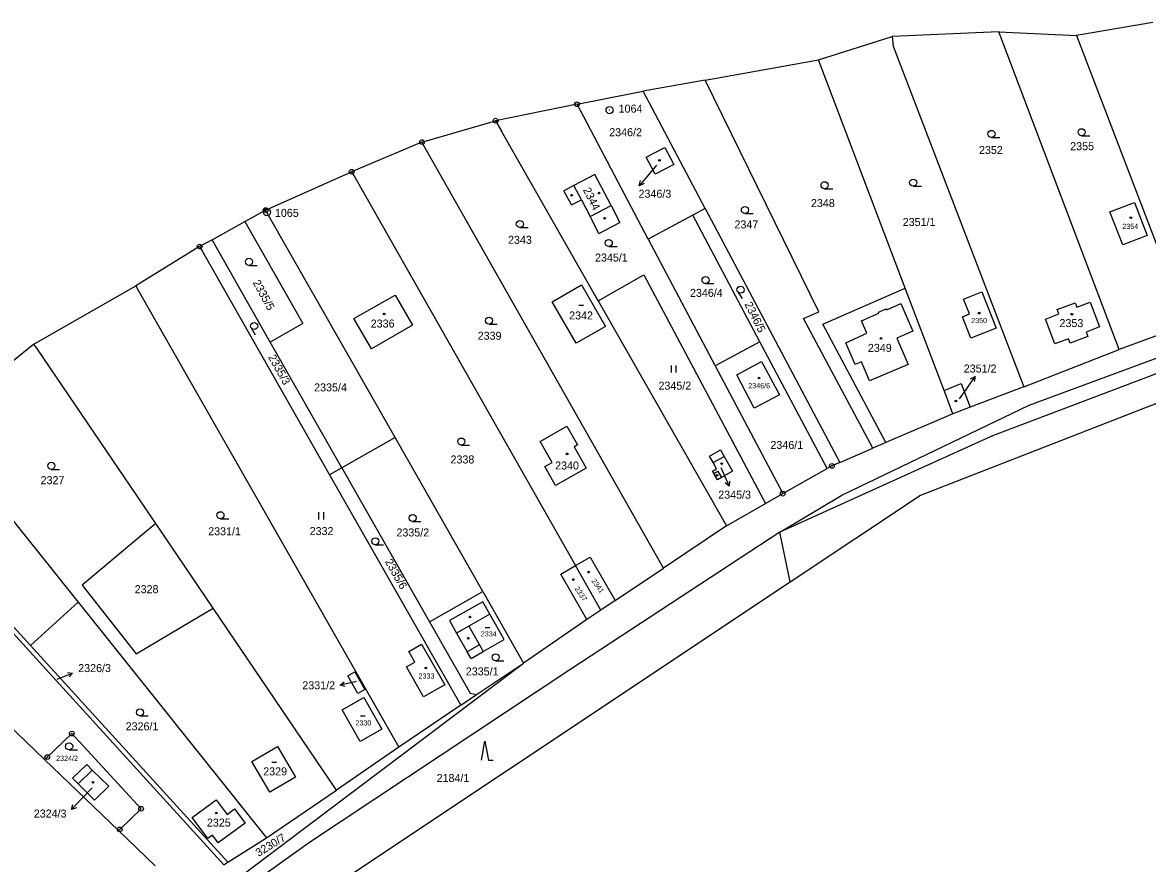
# Model space of a CAD drawing. Extents: x -736345 to -729997, y -1130177 to -1122501.
# Drawn here: x -734408.5 to -734169.6, y -1128988.6 to -1128810 of the extents above; entities that cross this region are included whole.
import ezdxf

# ---------------------------------------------------------------- set-up
doc = ezdxf.new("R2010")
doc.units = 0
for name, color, linetype in [('Vrstva 1', 7, 'Continuous'), ('Vrstva 13', 7, 'Continuous'), ('Vrstva 16', 7, 'Continuous'), ('Vrstva 17', 7, 'Continuous'), ('Vrstva 18', 7, 'Continuous'), ('Vrstva 19', 7, 'Continuous'), ('Vrstva 25', 7, 'Continuous'), ('Vrstva 4', 7, 'Continuous')]:
    doc.layers.add(name, color=color, linetype=linetype)

msp = doc.modelspace()

# ---------------------------------------------------------------- linework, layer by layer
at = {"layer": 'Vrstva 1'}
for points in [[(-734175.55, -1128879.43), (-734201.13, -1128811.92)], [(-734223.81, -1128812.9), (-734223.55, -1128814.98)], [(-734184.68, -1128812.7), (-734161.13, -1128874.06)], [(-734223.55, -1128814.98), (-734195.81, -1128887.3)], [(-734221, -1128866.4), (-734239.43, -1128817.9)], [(-734239.4, -1128871.37), (-734263.48, -1128822.21)], [(-734263.51, -1128849.46), (-734276.7, -1128824.57)], [(-734275.58, -1128855.97), (-734290.72, -1128827.32)], [(-734308.02, -1128830.81), (-734306.73, -1128833.07)], [(-734286.23, -1128869.04), (-734306.73, -1128833.07)], [(-734272.34, -1128925.84), (-734323.66, -1128835.35)], [(-734276.01, -1128838.57), (-734272.07, -1128836.49)], [(-734272.07, -1128836.49), (-734270.17, -1128840.09)], [(-734274.11, -1128842.17), (-734276.01, -1128838.57)], [(-734270.17, -1128840.09), (-734274.11, -1128842.17)], [(-734338.58, -1128841.66), (-734337.94, -1128842.77)], [(-734337.94, -1128842.77), (-734291.04, -1128925.3)], [(-734286.93, -1128842.25), (-734291.38, -1128844.58)], [(-734283.5, -1128848.82), (-734286.93, -1128842.25)], [(-734044.47, -1128842.87), (-734217.97, -1128910.48)], [(-734291.38, -1128844.58), (-734293.5, -1128845.69)], [(-734291.92, -1128848.71), (-734293.5, -1128845.69)], [(-734291.92, -1128848.71), (-734289.8, -1128847.61)], [(-734289.8, -1128847.61), (-734287.95, -1128851.15)], [(-734329.36, -1128898.07), (-734356.86, -1128849.81)], [(-734283.5, -1128848.82), (-734281.63, -1128852.4)], [(-734263.51, -1128849.46), (-734266.15, -1128850.88)], [(-734263.51, -1128849.46), (-734234.92, -1128903.41)], [(-734177.58, -1128850.2), (-734172.35, -1128848.19)], [(-734172.35, -1128848.19), (-734169.65, -1128855.2)], [(-734361.24, -1128852.22), (-734348.92, -1128873.86)], [(-734286.07, -1128854.75), (-734287.95, -1128851.15)], [(-734286.07, -1128854.75), (-734281.63, -1128852.4)], [(-734266.15, -1128850.88), (-734275.58, -1128855.97)], [(-734251.89, -1128877.76), (-734266.15, -1128850.88)], [(-734174.84, -1128857.19), (-734177.58, -1128850.2)], [(-734355.87, -1128877.81), (-734368.24, -1128856.09)], [(-734275.58, -1128855.97), (-734261.35, -1128882.89)], [(-734169.65, -1128855.2), (-734174.84, -1128857.19)], [(-734370.86, -1128857.54), (-734370.24, -1128858.62)], [(-734370.24, -1128858.62), (-734343.28, -1128906)], [(-734104.36, -1128860.59), (-734202.48, -1128897.74)], [(-734286.23, -1128869.04), (-734276.54, -1128863.52)], [(-734276.54, -1128863.52), (-734250.69, -1128912.1)], [(-734384.45, -1128865.86), (-734383.84, -1128866.92)], [(-734295.99, -1128869.25), (-734289.75, -1128865.67)], [(-734289.75, -1128865.67), (-734284.67, -1128874.53)], [(-734238.54, -1128874.04), (-734221, -1128866.4)], [(-734212.77, -1128888.09), (-734221, -1128866.4)], [(-734383.84, -1128866.92), (-734328.54, -1128963.82)], [(-734338.14, -1128872.82), (-734329.37, -1128867.85)], [(-734329.37, -1128867.85), (-734325.69, -1128874.26)], [(-734290.93, -1128878.07), (-734295.99, -1128869.25)], [(-734286.23, -1128869.04), (-734259, -1128916.82)], [(-734208.65, -1128868.68), (-734204.73, -1128867.15)], [(-734207.37, -1128871.82), (-734208.65, -1128868.68)], [(-734204.73, -1128867.15), (-734201.71, -1128874.85)], [(-734242.6, -1128872.8), (-734239.4, -1128871.37)], [(-734188.72, -1128870.92), (-734184.95, -1128869.49)], [(-734188.37, -1128871.85), (-734188.72, -1128870.92)], [(-734184.95, -1128869.49), (-734184.6, -1128870.42)], [(-734184.6, -1128870.42), (-734181.75, -1128869.34)], [(-734181.75, -1128869.34), (-734179.74, -1128874.62)], [(-734348.92, -1128873.86), (-734355.87, -1128877.81)], [(-734334.39, -1128879.25), (-734338.14, -1128872.82)], [(-734227.87, -1128900.37), (-734242.6, -1128872.8)], [(-734225.12, -1128899.18), (-734238.54, -1128874.04)], [(-734208.88, -1128872.44), (-734207.37, -1128871.82)], [(-734207.08, -1128876.98), (-734208.88, -1128872.44)], [(-734194.67, -1128891.21), (-734144.71, -1128872.72)], [(-734191.23, -1128872.94), (-734188.37, -1128871.85)], [(-734189.22, -1128878.22), (-734191.23, -1128872.94)], [(-734325.69, -1128874.26), (-734334.39, -1128879.25)], [(-734284.67, -1128874.53), (-734290.93, -1128878.07)], [(-734201.71, -1128874.85), (-734207.08, -1128876.98)], [(-734179.74, -1128874.62), (-734182.58, -1128875.7)], [(-734182.58, -1128875.7), (-734182.22, -1128876.65)], [(-734161.13, -1128874.06), (-734175.55, -1128879.43)], [(-734405.32, -1128879.31), (-734406.05, -1128878.24)], [(-734340.67, -1128904.51), (-734355.87, -1128877.81)], [(-734251.89, -1128877.76), (-734261.35, -1128882.89)], [(-734237.62, -1128904.7), (-734251.89, -1128877.76)], [(-734186.38, -1128877.15), (-734189.22, -1128878.22)], [(-734186.02, -1128878.09), (-734186.38, -1128877.15)], [(-734182.22, -1128876.65), (-734186.02, -1128878.09)], [(-734380.2, -1128916.33), (-734405.32, -1128879.31)], [(-734195.81, -1128887.3), (-734175.55, -1128879.43)], [(-734261.35, -1128882.89), (-734247.02, -1128910.01)], [(-734256.81, -1128884.79), (-734251.52, -1128881.92)], [(-734251.52, -1128881.92), (-734247.74, -1128889.05)], [(-734253.07, -1128891.87), (-734256.81, -1128884.79)], [(-734212.77, -1128888.09), (-734209.13, -1128886.62)], [(-734212.41, -1128889.03), (-734212.77, -1128888.09)], [(-734209.13, -1128886.62), (-734207.24, -1128891.66)], [(-734195.81, -1128887.3), (-734207.24, -1128891.66)], [(-734247.74, -1128889.05), (-734253.07, -1128891.87)], [(-734210.88, -1128893.05), (-734212.41, -1128889.03)], [(-734234.48, -1128910.31), (-734194.67, -1128891.21)], [(-734210.88, -1128893.05), (-734225.12, -1128899.18)], [(-734207.24, -1128891.66), (-734210.88, -1128893.05)], [(-734426.53, -1128895.73), (-734396.68, -1128933.07)], [(-734298.55, -1128898.95), (-734292.85, -1128895.69)], [(-734292.85, -1128895.69), (-734290.6, -1128899.64)], [(-734202.48, -1128897.74), (-734247.62, -1128918.22)], [(-734329.36, -1128898.07), (-734340.67, -1128904.51)], [(-734310.71, -1128930.81), (-734329.36, -1128898.07)], [(-734296.02, -1128903.42), (-734298.55, -1128898.95)], [(-734290.6, -1128899.64), (-734291.35, -1128900.07)], [(-734291.35, -1128900.07), (-734288.79, -1128904.58)], [(-734225.12, -1128899.18), (-734227.87, -1128900.37)], [(-734262.6, -1128902.06), (-734260.28, -1128900.69)], [(-734261.84, -1128903.4), (-734262.6, -1128902.06)], [(-734260.28, -1128900.69), (-734259.49, -1128902.1)], [(-734259.49, -1128902.1), (-734257.69, -1128905.27)], [(-734234.92, -1128903.41), (-734227.87, -1128900.37)], [(-734340.67, -1128904.51), (-734343.28, -1128906)], [(-734340.67, -1128904.51), (-734322.02, -1128937.25)], [(-734297.55, -1128904.28), (-734296.02, -1128903.42)], [(-734295.3, -1128908.25), (-734297.55, -1128904.28)], [(-734288.79, -1128904.58), (-734295.3, -1128908.25)], [(-734261.96, -1128905.21), (-734261.09, -1128904.72)], [(-734261.09, -1128904.72), (-734261.84, -1128903.4)], [(-734247.02, -1128910.01), (-734237.62, -1128904.7)], [(-734236.58, -1128904.12), (-734237.62, -1128904.7)], [(-734234.92, -1128903.41), (-734236.58, -1128904.12)], [(-734406.77, -1128942.26), (-734439.96, -1128905.8)], [(-734439.82, -1128907.45), (-734365.73, -1128988.82)], [(-734343.28, -1128906), (-734315.43, -1128954.92)], [(-734261.67, -1128905.72), (-734261.96, -1128905.21)], [(-734260.9, -1128907.08), (-734261.67, -1128905.72)], [(-734260.03, -1128906.59), (-734260.9, -1128907.08)], [(-734257.69, -1128905.27), (-734260.03, -1128906.59)], [(-734259, -1128916.82), (-734250.69, -1128912.1)], [(-734250.69, -1128912.1), (-734247.02, -1128910.01)], [(-734247.62, -1128918.22), (-734234.48, -1128910.31)], [(-734245.42, -1128928.76), (-734217.97, -1128910.48)], [(-734380.2, -1128916.33), (-734383.08, -1128918.76)], [(-734367.97, -1128934.35), (-734380.2, -1128916.33)], [(-734259, -1128916.82), (-734272.34, -1128925.84)], [(-734403.78, -1128966.49), (-734454.03, -1128918.18)], [(-734383.08, -1128918.76), (-734395.78, -1128929.48)], [(-734247.62, -1128918.22), (-734292.04, -1128947.31)], [(-734245.42, -1128928.76), (-734247.62, -1128918.22)], [(-734291.04, -1128925.3), (-734287.96, -1128923.52)], [(-734287.96, -1128923.52), (-734282.65, -1128932.71)], [(-734294.19, -1128927.13), (-734291.04, -1128925.3)], [(-734285.68, -1128934.73), (-734291.04, -1128925.3)], [(-734282.65, -1128932.71), (-734272.34, -1128925.84)], [(-734365.29, -1129008.59), (-734245.42, -1128928.76)], [(-734288.61, -1128936.74), (-734294.19, -1128927.13)], [(-734395.78, -1128929.48), (-734384.34, -1128944.02)], [(-734322.02, -1128937.25), (-734310.71, -1128930.81)], [(-734310.71, -1128930.81), (-734302.06, -1128946)], [(-734406.77, -1128942.26), (-734396.68, -1128933.07)], [(-734396.68, -1128933.07), (-734356.7, -1128983.08)], [(-734310.69, -1128933.01), (-734317.83, -1128936.94)], [(-734309.21, -1128935.62), (-734310.69, -1128933.01)], [(-734282.65, -1128932.71), (-734285.68, -1128934.73)], [(-734372.64, -1128937.11), (-734367.97, -1128934.35)], [(-734341.78, -1128972.95), (-734367.97, -1128934.35)], [(-734306.16, -1128941.01), (-734309.21, -1128935.62)], [(-734285.68, -1128934.73), (-734288.61, -1128936.74)], [(-734384.34, -1128944.02), (-734372.64, -1128937.11)], [(-734322.02, -1128937.25), (-734313.41, -1128952.37)], [(-734317.83, -1128936.94), (-734316.29, -1128939.63)], [(-734288.61, -1128936.74), (-734302.06, -1128946)], [(-734316.29, -1128939.63), (-734314.03, -1128943.6)], [(-734406.77, -1128942.26), (-734364.87, -1128988.28)], [(-734326.45, -1128943.53), (-734323.73, -1128941.97)], [(-734323.73, -1128941.97), (-734318.82, -1128950.61)], [(-734310.64, -1128943.55), (-734306.16, -1128941.01)], [(-734325.16, -1128945.79), (-734326.45, -1128943.53)], [(-734313.22, -1128945.02), (-734314.03, -1128943.6)], [(-734313.22, -1128945.02), (-734310.64, -1128943.55)], [(-734362.98, -1128991.91), (-734302.06, -1128946)], [(-734292.04, -1128947.31), (-734347.55, -1128984.09)], [(-734339.4, -1128948.72), (-734337.88, -1128947.85)], [(-734337.88, -1128947.85), (-734335.75, -1128951.59)], [(-734326.9, -1128946.79), (-734325.16, -1128945.79)], [(-734323.29, -1128953.15), (-734326.9, -1128946.79)], [(-734312.08, -1128952.69), (-734302.06, -1128946)], [(-734337.27, -1128952.45), (-734339.4, -1128948.72)], [(-734335.75, -1128951.59), (-734337.27, -1128952.45)], [(-734318.82, -1128950.61), (-734323.29, -1128953.15)], [(-734315.43, -1128954.92), (-734312.08, -1128952.69)], [(-734313.41, -1128952.37), (-734312.08, -1128952.69)], [(-734340.61, -1128955.9), (-734335.97, -1128953.27)], [(-734335.97, -1128953.27), (-734332.14, -1128960.04)], [(-734315.43, -1128954.92), (-734328.54, -1128963.82)], [(-734336.79, -1128962.67), (-734340.61, -1128955.9)], [(-734332.14, -1128960.04), (-734336.79, -1128962.67)], [(-734403.22, -1128965.95), (-734398.02, -1128960.95)], [(-734398.02, -1128960.95), (-734383.29, -1128976.94)], [(-734359.78, -1128966.88), (-734354.32, -1128963.7)], [(-734354.32, -1128963.7), (-734350.52, -1128970.23)], [(-734328.54, -1128963.82), (-734341.78, -1128972.95)], [(-734403.78, -1128966.49), (-734403.22, -1128965.95)], [(-734388.1, -1128981.56), (-734403.78, -1128966.49)], [(-734355.98, -1128973.39), (-734359.78, -1128966.88)], [(-734397.87, -1128970.42), (-734394.84, -1128967.56)], [(-734394.84, -1128967.56), (-734393.71, -1128968.74)], [(-734393.71, -1128968.74), (-734390.12, -1128972.16)], [(-734396.68, -1128971.61), (-734397.87, -1128970.42)], [(-734393.17, -1128975.11), (-734396.68, -1128971.61)], [(-734350.52, -1128970.23), (-734355.98, -1128973.39)], [(-734390.12, -1128972.16), (-734393.17, -1128975.11)], [(-734356.7, -1128983.08), (-734341.78, -1128972.95)], [(-734372.43, -1128978.77), (-734367.38, -1128975.04)], [(-734367.38, -1128975.04), (-734365.01, -1128978.12)], [(-734383.29, -1128976.94), (-734387.84, -1128981.31)], [(-734369.12, -1128983.25), (-734372.43, -1128978.77)], [(-734365.01, -1128978.12), (-734363.47, -1128976.93)], [(-734363.47, -1128976.93), (-734361.22, -1128979.96)], [(-734387.84, -1128981.31), (-734388.1, -1128981.56)], [(-734380.33, -1128989.03), (-734388.1, -1128981.56)], [(-734361.22, -1128979.96), (-734366.9, -1128984.17)], [(-734368.14, -1128982.51), (-734369.12, -1128983.25)], [(-734366.9, -1128984.17), (-734368.14, -1128982.51)], [(-734364.87, -1128988.28), (-734356.7, -1128983.08)], [(-734347.55, -1128984.09), (-734361.23, -1128993.88)], [(-734365.73, -1128988.82), (-734364.87, -1128988.28)]]:
    msp.add_lwpolyline(points, dxfattribs=at)
at = {"layer": 'Vrstva 13'}
for points in [[(-734201.13, -1128811.92), (-734223.81, -1128812.9)], [(-734201.13, -1128811.92), (-734184.68, -1128812.7)], [(-734168.46, -1128809.96), (-734184.68, -1128812.7)], [(-734239.43, -1128817.9), (-734223.81, -1128812.9)], [(-734263.48, -1128822.21), (-734239.43, -1128817.9)], [(-734263.48, -1128822.21), (-734276.7, -1128824.57)], [(-734290.72, -1128827.32), (-734278.48, -1128824.89)], [(-734278.48, -1128824.89), (-734276.7, -1128824.57)], [(-734290.72, -1128827.32), (-734308.02, -1128830.81)], [(-734323.66, -1128835.35), (-734308.02, -1128830.81)], [(-734323.66, -1128835.35), (-734338.58, -1128841.66)], [(-734356.86, -1128849.81), (-734338.58, -1128841.66)], [(-734361.24, -1128852.22), (-734356.86, -1128849.81)], [(-734368.24, -1128856.09), (-734361.24, -1128852.22)], [(-734368.24, -1128856.09), (-734370.86, -1128857.54)], [(-734370.86, -1128857.54), (-734384.45, -1128865.86)], [(-734406.05, -1128878.24), (-734384.45, -1128865.86)], [(-734406.05, -1128878.24), (-734426.99, -1128895.15)]]:
    msp.add_lwpolyline(points, dxfattribs=at)
at = {"layer": 'Vrstva 16'}
for points in [[(-734273.87, -1128840.28), (-734275.57, -1128842.32)], [(-734209.46, -1128889.86), (-734207.89, -1128887.58)], [(-734260.18, -1128904.48), (-734259.63, -1128905.71)], [(-734401.12, -1128949.39), (-734400.64, -1128949.2)], [(-734337.65, -1128949.93), (-734338.11, -1128950.03)], [(-734393.67, -1128972.45), (-734396.02, -1128974.92)]]:
    msp.add_lwpolyline(points, dxfattribs=at)
at = {"layer": 'Vrstva 25'}
for points in [[(-734202.7, -1128834.37), (-734200.95, -1128834.37)], [(-734183.56, -1128834.01), (-734181.81, -1128834.01)], [(-734275.57, -1128842.32), (-734277.49, -1128844.624)], [(-734276.466, -1128844.176), (-734277.49, -1128844.624), (-734277.234, -1128843.536)], [(-734238.15, -1128845.27), (-734236.4, -1128845.27)], [(-734219.33, -1128844.71), (-734217.58, -1128844.71)], [(-734255.07, -1128850.52), (-734253.32, -1128850.52)], [(-734302.86, -1128853.51), (-734301.11, -1128853.51)], [(-734283.98, -1128857.52), (-734282.23, -1128857.52)], [(-734360.39, -1128861.53), (-734358.64, -1128861.53)], [(-734263.42, -1128865.41), (-734261.67, -1128865.41)], [(-734256.63, -1128867.11), (-734255.683, -1128868.58)], [(-734290.31, -1128870.01), (-734289.31, -1128870.01)], [(-734309.41, -1128874.02), (-734307.66, -1128874.02)], [(-734359.94, -1128874.79), (-734359.087, -1128876.317)], [(-734270.687, -1128884.295), (-734270.687, -1128882.795)], [(-734269.653, -1128884.295), (-734269.653, -1128882.795)], [(-734207.89, -1128887.58), (-734206.191, -1128885.108)], [(-734207.17, -1128885.649), (-734206.191, -1128885.108), (-734206.346, -1128886.215)], [(-734315.29, -1128899.7), (-734313.54, -1128899.7)], [(-734402.37, -1128904.86), (-734400.62, -1128904.86)], [(-734259.63, -1128905.71), (-734258.41, -1128908.45)], [(-734258.36, -1128907.333), (-734258.41, -1128908.45), (-734259.274, -1128907.74)], [(-734345.557, -1128915.475), (-734345.557, -1128913.975)], [(-734344.523, -1128915.475), (-734344.523, -1128913.975)], [(-734366.45, -1128915.34), (-734364.7, -1128915.34)], [(-734325.63, -1128915.93), (-734323.88, -1128915.93)], [(-734333.54, -1128920.88), (-734331.79, -1128920.88)], [(-734310.26, -1128938.41), (-734309.26, -1128938.41)], [(-734308.01, -1128945.51), (-734306.26, -1128945.51)], [(-734400.64, -1128949.2), (-734397.849, -1128948.101)], [(-734398.963, -1128948.002), (-734397.849, -1128948.101), (-734398.596, -1128948.933)], [(-734339.963, -1128950.931), (-734341.045, -1128950.648), (-734340.17, -1128949.954)], [(-734338.11, -1128950.03), (-734341.045, -1128950.648)], [(-734383.54, -1128957.2), (-734381.79, -1128957.2)], [(-734336.68, -1128957.19), (-734335.68, -1128957.19)], [(-734398.58, -1128964.42), (-734396.83, -1128964.42)], [(-734311.03, -1128966.58), (-734310.28, -1128962.58), (-734309.53, -1128966.58), (-734308.53, -1128966.58)], [(-734355.52, -1128967.01), (-734354.52, -1128967.01)], [(-734396.02, -1128974.92), (-734398.092, -1128977.088)], [(-734397.04, -1128976.711), (-734398.092, -1128977.088), (-734397.763, -1128976.02)]]:
    msp.add_lwpolyline(points, dxfattribs=at)
for centre, radius in [((-734290.72, -1128827.32), 0.5), ((-734290.72, -1128827.32), 0.032), ((-734283.81, -1128828.57), 0.75), ((-734283.81, -1128828.57), 0.032), ((-734308.02, -1128830.81), 0.5), ((-734308.02, -1128830.81), 0.032), ((-734202.7, -1128833.62), 0.75), ((-734183.56, -1128833.26), 0.75), ((-734323.66, -1128835.35), 0.5), ((-734323.66, -1128835.35), 0.032), ((-734273.22, -1128839.24), 0.175), ((-734338.58, -1128841.66), 0.5), ((-734338.58, -1128841.66), 0.032), ((-734238.15, -1128844.52), 0.75), ((-734219.33, -1128843.96), 0.75), ((-734291.86, -1128846.63), 0.175), ((-734286.07, -1128846.19), 0.175), ((-734356.86, -1128849.81), 0.5), ((-734356.56, -1128850.25), 0.75), ((-734356.86, -1128849.81), 0.032), ((-734255.07, -1128849.77), 0.75), ((-734356.56, -1128850.25), 0.032), ((-734302.86, -1128852.76), 0.75), ((-734284.85, -1128851.53), 0.175), ((-734173.12, -1128851.42), 0.175), ((-734370.86, -1128857.54), 0.5), ((-734283.98, -1128856.77), 0.75), ((-734370.86, -1128857.54), 0.032), ((-734360.39, -1128860.78), 0.75), ((-734263.42, -1128864.66), 0.75), ((-734256, -1128866.704), 0.749), ((-734205.33, -1128871.67), 0.175), ((-734359.286, -1128874.424), 0.749), ((-734331.69, -1128871.87), 0.175), ((-734309.41, -1128873.27), 0.75), ((-734185.62, -1128871.91), 0.175), ((-734226.16, -1128877.05), 0.175), ((-734252.07, -1128885.46), 0.175), ((-734210.27, -1128890.34), 0.175), ((-734315.29, -1128898.95), 0.75), ((-734292.82, -1128901.56), 0.175), ((-734402.37, -1128904.11), 0.75), ((-734260.01, -1128903.64), 0.175), ((-734236.58, -1128904.12), 0.5), ((-734236.58, -1128904.12), 0.032), ((-734260.96, -1128906.13), 0.175), ((-734247.02, -1128910.01), 0.5), ((-734247.02, -1128910.01), 0.032), ((-734366.45, -1128914.59), 0.75), ((-734325.63, -1128915.18), 0.75), ((-734333.54, -1128920.13), 0.75), ((-734288.24, -1128926.67), 0.175), ((-734291.5, -1128928.25), 0.175), ((-734313.46, -1128936.21), 0.175), ((-734313.81, -1128940.71), 0.175), ((-734308.01, -1128944.76), 0.75), ((-734322.83, -1128947.04), 0.175), ((-734383.54, -1128956.45), 0.75), ((-734398.02, -1128960.95), 0.5), ((-734398.02, -1128960.95), 0.0316), ((-734398.58, -1128963.67), 0.75), ((-734403.22, -1128965.95), 0.5), ((-734403.22, -1128965.95), 0.0311), ((-734393.53, -1128971.3), 0.175), ((-734383.29, -1128976.94), 0.499), ((-734383.29, -1128976.94), 0.0318), ((-734367.33, -1128977.84), 0.175), ((-734387.84, -1128981.31), 0.5), ((-734387.84, -1128981.31), 0.0313)]:
    msp.add_circle(centre, radius, dxfattribs=at)
at = {"layer": 'Vrstva 4'}
for points in [[(-734289.8, -1128847.61), (-734291.38, -1128844.58)], [(-734287.95, -1128851.15), (-734283.5, -1128848.82)], [(-734226.7, -1128871.46), (-734225.05, -1128870.73)], [(-734226.61, -1128871.67), (-734226.7, -1128871.46)], [(-734225.05, -1128870.73), (-734224.95, -1128870.96)], [(-734224.95, -1128870.96), (-734221.98, -1128869.65)], [(-734221.98, -1128869.65), (-734219.43, -1128875.5)], [(-734230.34, -1128873.31), (-734226.61, -1128871.67)], [(-734229.15, -1128875.91), (-734230.34, -1128873.31)], [(-734233.64, -1128877.95), (-734229.15, -1128875.91)], [(-734219.43, -1128875.5), (-734222.8, -1128876.97)], [(-734231.63, -1128882.62), (-734233.64, -1128877.95)], [(-734222.8, -1128876.97), (-734220.41, -1128882.55)], [(-734230.3, -1128882.05), (-734231.63, -1128882.62)], [(-734228.59, -1128886.04), (-734230.3, -1128882.05)], [(-734220.41, -1128882.55), (-734228.59, -1128886.04)], [(-734261.84, -1128903.4), (-734259.49, -1128902.1)], [(-734261.67, -1128905.72), (-734260.81, -1128905.22)], [(-734260.81, -1128905.22), (-734260.03, -1128906.59)], [(-734309.21, -1128935.62), (-734313.7, -1128938.16)], [(-734313.7, -1128938.16), (-734316.29, -1128939.63)], [(-734313.7, -1128938.16), (-734311.45, -1128942.12)], [(-734311.45, -1128942.12), (-734314.03, -1128943.6)], [(-734311.45, -1128942.12), (-734310.64, -1128943.55)], [(-734396.68, -1128971.61), (-734393.71, -1128968.74)]]:
    msp.add_lwpolyline(points, dxfattribs=at)

# ---------------------------------------------------------------- texts
at = {"layer": 'Vrstva 16'}
for s, p in [('2346/3', (-734277.657, -1128847.17)), ('2351/2', (-734208.588, -1128884.29)), ('2345/3', (-734260.73, -1128911.08)), ('2326/3', (-734396.65, -1128947.9)), ('2331/2', (-734349.057, -1128951.56)), ('2324/3', (-734406.087, -1128978.79))]:
    msp.add_text(s, height=1.7, dxfattribs=at).set_placement(p)
at = {"layer": 'Vrstva 17'}
for s, p in [('1064', (-734281.88, -1128829.1)), ('1065', (-734354.87, -1128851.24))]:
    msp.add_text(s, height=1.7, dxfattribs=at).set_placement(p)
at = {"layer": 'Vrstva 18'}
for s, height, p in [('2346/2', 1.7, (-734283.88, -1128834.11)), ('2355', 1.7, (-734185.98, -1128837.08)), ('2352', 1.7, (-734205.36, -1128837.88)), ('2348', 1.7, (-734241.04, -1128849.15)), ('2347', 1.7, (-734257.28, -1128853.69)), ('2351/1', 1.7, (-734221.558, -1128853.18)), ('2343', 1.7, (-734305.38, -1128856.96)), ('2345/1', 1.7, (-734286.9, -1128860.72)), ('2346/4', 1.7, (-734266.73, -1128868.22)), ('2339', 1.7, (-734311.82, -1128877.33)), ('2335/4', 1.7, (-734346.55, -1128888.3)), ('2345/2', 1.7, (-734273.42, -1128887.93)), ('2346/1', 1.7, (-734249.65, -1128900.52)), ('2338', 1.7, (-734317.59, -1128903.6)), ('2327', 1.7, (-734404.64, -1128908)), ('2331/1', 1.7, (-734369.05, -1128918.85)), ('2332', 1.7, (-734347.5, -1128918.81)), ('2335/2', 1.7, (-734329.07, -1128919.1)), ('2328', 1.7, (-734384.66, -1128931.15)), ('2335/1', 1.7, (-734314.34, -1128948.61)), ('2326/3', 0.1, (-734400.92, -1128949.19)), ('2331/2', 0.1, (-734337.45, -1128949.73)), ('2326/1', 1.7, (-734386.58, -1128960.27)), ('2324/2', 1.1, (-734401.35, -1128966.78)), ('2184/1', 1.7, (-734320.54, -1128971.24))]:
    msp.add_text(s, height=height, dxfattribs=at).set_placement(p)
for s, rotation, p in [('2335/5', 298.60237, (-734359.649, -1128865.169)), ('2346/5', 296.50236, (-734255.192, -1128869.769)), ('2335/3', 299.00238, (-734356.369, -1128881.017)), ('2335/6', 299.20238, (-734331.573, -1128924.427)), ('3230/7', 31.40025, (-734358.344, -1128987.156))]:
    msp.add_text(s, height=1.7, rotation=rotation, dxfattribs=at).set_placement(p)
at = {"layer": 'Vrstva 19'}
for s, height, p in [('2346/3', 0.1, (-734273.67, -1128840.08)), ('2354', 1.1, (-734174.91, -1128853.8)), ('2342', 1.7, (-734292.4, -1128873.02)), ('2336', 1.7, (-734334.53, -1128874.74)), ('2350', 1.1, (-734207.02, -1128873.8)), ('2353', 1.7, (-734188.26, -1128874.64)), ('2349', 1.7, (-734228.95, -1128879.91)), ('2346/6', 1.1, (-734254.36, -1128887.64)), ('2351/2', 0.1, (-734209.474, -1128889.66)), ('2340', 1.7, (-734295.37, -1128904.88)), ('2345/3', 0.1, (-734259.98, -1128904.28)), ('2334', 1.1, (-734311.17, -1128940.33)), ('2333', 1.1, (-734324.38, -1128949.29)), ('2330', 1.1, (-734337.78, -1128959.24)), ('2329', 1.7, (-734357.36, -1128969.84)), ('2324/3', 0.1, (-734393.47, -1128972.25)), ('2325', 1.7, (-734369.32, -1128980.71))]:
    msp.add_text(s, height=height, dxfattribs=at).set_placement(p)
for s, height, rotation, p in [('2344', 1.7, 296.30236, (-734289.493, -1128845.48)), ('2341', 1.1, 305.60243, (-734287.721, -1128928.536)), ('2337', 1.1, 303.90242, (-734291.293, -1128930.184))]:
    msp.add_text(s, height=height, rotation=rotation, dxfattribs=at).set_placement(p)

doc.saveas('drawing.dxf')
